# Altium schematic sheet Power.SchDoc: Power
size B; Date: 12/18/2013; DrawnBy: David McCoy; Engineer: David McCoy (Cospan Design); DocumentNumber: 10; Revision: C; SheetNumber: 10; SheetTotal: 10
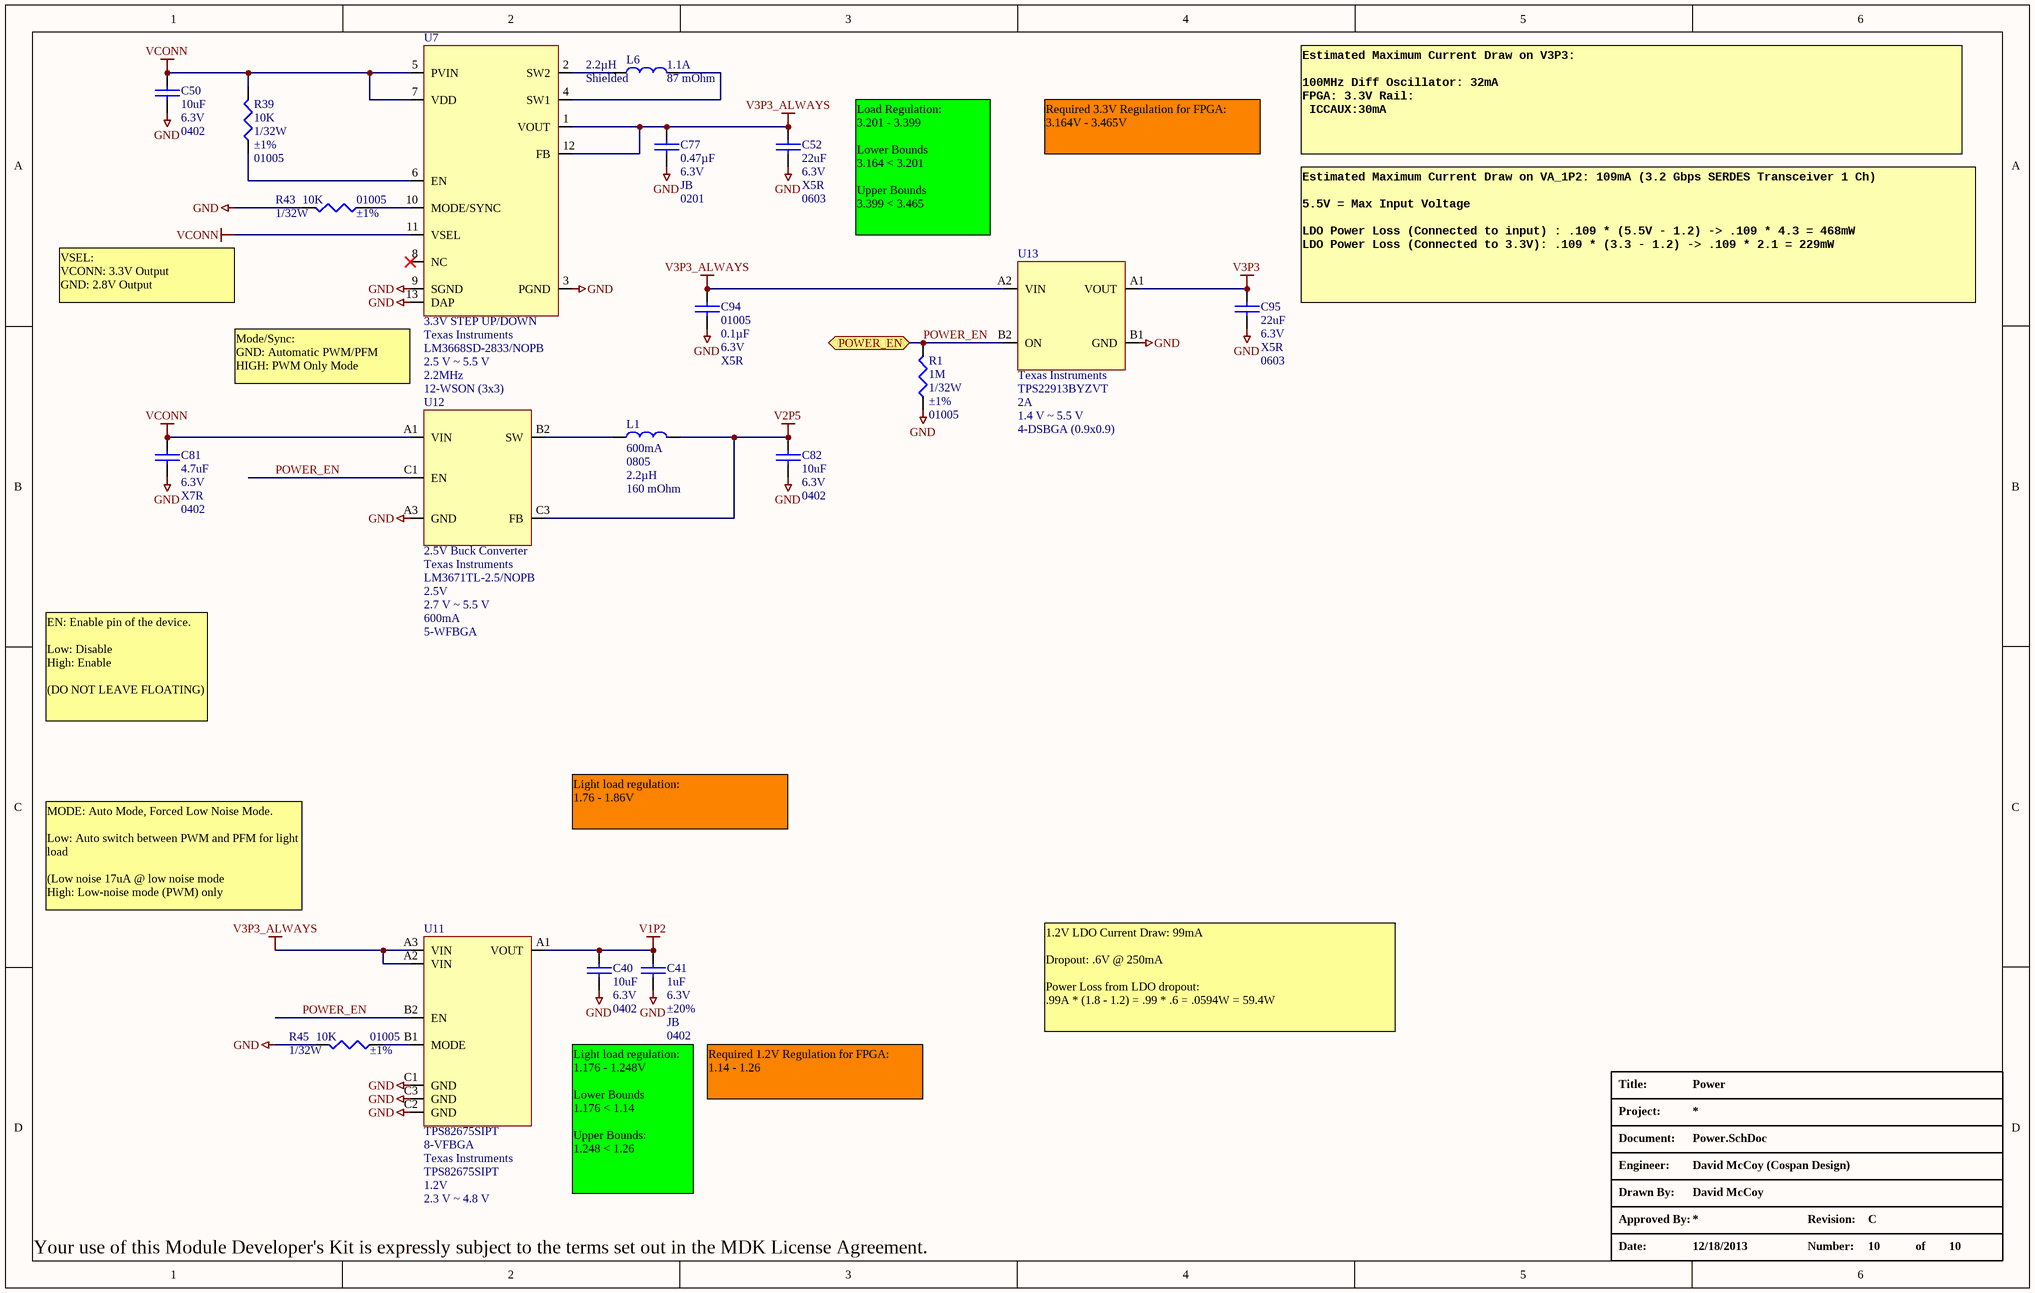
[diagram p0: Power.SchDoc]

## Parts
C40  Voltage - Rated: 6.3V  Package / Case: 0402  [C_0402]  (hidden comment: 10uF)
C41  Voltage - Rated: 6.3V  Tolerance: ±20%  Temperature Coefficient: JB  Package / Case: 0402  [C_0402]  (hidden comment: 1uF)
C50  Voltage - Rated: 6.3V  Package / Case: 0402  [C_0402]  (hidden comment: 10uF)
C52  Voltage - Rated: 6.3V  Temperature Coefficient: X5R  Package / Case: 0603  [C_ERA-0603]  (hidden comment: 22uF)
C77  Voltage - Rated: 6.3V  Temperature Coefficient: JB  Package / Case: 0201  [CAPC0201]  (hidden comment: 0.47µF)
C81  Voltage - Rated: 6.3V  Temperature Coefficient: X7R  Package / Case: 0402  [C_0402]  (hidden comment: 4.7uF)
C82  Voltage - Rated: 6.3V  Package / Case: 0402  [C_0402]  (hidden comment: 10uF)
C94  Package / Case: 01005  Capacitance: 0.1µF  Voltage - Rated: 6.3V  Temperature Coefficient: X5R  [C_01005]  (hidden comment: 0.1uF)
C95  Voltage - Rated: 6.3V  Temperature Coefficient: X5R  Package / Case: 0603  [C_ERA-0603]  (hidden comment: 22uF)
L1  Current: 600mA  Package / Case: 0805  Inductance: 2.2µH  DC Resistance (DCR): 160 mOhm  [C_ERA-0805]  (hidden comment: 2.2uH)
L6  Inductance: 2.2µH  Current - Saturation: 1.1A  Shielding: Shielded  DC Resistance (DCR): 87 mOhm  [L_SMD_2.2uH]  (hidden comment: 2.2uH Wirewound)
R1  Resistance In Ohms: 1M  Power (Watts): 1/32W  Tolerance: ±1%  Case: 01005  [R_01005]  (hidden comment: 1M Ohms)
R39  Power (Watts): 1/32W  Tolerance: ±1%  Case: 01005  [R_01005]  (hidden comment: 10K)
R43  Power (Watts): 1/32W  Tolerance: ±1%  Case: 01005  [R_01005]  (hidden comment: 10K)
R45  Power (Watts): 1/32W  Tolerance: ±1%  Case: 01005  [R_01005]  (hidden comment: 10K)
U7  3.3V STEP UP/DOWN  Manufacturer: Texas Instruments  Manufacturer Part Number: LM3668SD-2833/NOPB  Voltage - Input: 2.5 V ~ 5.5 V  Frequency - Switching: 2.2MHz  Supplier Device Package: 12-WSON (3x3)  [QFN40P300X300X80_HS-13L]
U11  TPS82675SIPT  Package / Case: 8-VFBGA  Manufacturer: Texas Instruments  Voltage - Output: 1.2V  Voltage - Input: 2.3 V ~ 4.8 V  [MICRP SIP]
U12  2.5V Buck Converter  Manufacturer: Texas Instruments  Manufacturer Part Number: LM3671TL-2.5/NOPB  Voltage - Output: 2.5V  Voltage - Input: 2.7 V ~ 5.5 V  Current - Output: 600mA  Package / Case: 5-WFBGA  [BGA4C50P2X2_105X138X60]
U13  Manufacturer: Texas Instruments  Manufacturer Part Number: TPS22913BYZVT  Current Limit: 2A  Voltage - Input: 1.4 V ~ 5.5 V  Supplier Device Package: 4-DSBGA (0.9x0.9)  [DSBGA4 _.5MM]  (hidden comment: Power Switch)

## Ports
POWER_EN

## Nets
GND: C40.1 C41.1 C50.1 C52.1 C77.1 C81.1 C82.1 C94.1 C95.1 R1.2 R43.1 R45.1 U7.3(PGND) U7.9(SGND) U7.13(DAP) U11.C1(GND) U11.C2(GND) U11.C3(GND) U12.A3(GND) U13.B1(GND)
V1P2: C40.2 C41.2 U11.A1(VOUT)
V2P5: C82.2 L1.2 U12.C3(FB)
V3P3: C95.2 U13.A1(VOUT)
V3P3_ALWAYS: C52.2 C77.2 C94.2 U7.1(VOUT) U7.12(FB) U11.A2(VIN) U11.A3(VIN) U13.A2(VIN)
VCONN: C50.2 C81.2 R39.1 U7.5(PVIN) U7.7(VDD) U7.11(VSEL) U12.A1(VIN)
POWER_EN: R1.1 U11.B2(EN) U12.C1(EN) U13.B2(ON) ; port POWER_EN
NetL1_1: L1.1 U12.B2(SW)
NetL6_1: L6.1 U7.2(SW2)
NetL6_2: L6.2 U7.4(SW1)
NetR39_2: R39.2 U7.6(EN)
NetR43_2: R43.2 U7.10(MODE/SYNC)
NetR45_2: R45.2 U11.B1(MODE)

Not connected (* = marked no-connect by the designer): U7 8(NC)*

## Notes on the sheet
- Required 3.3V Regulation for FPGA:
  3.164V - 3.465V
- Estimated Maximum Current Draw on V3P3:
  100MHz Diff Oscillator: 32mA
  FPGA: 3.3V Rail:
  ICCAUX:30mA
- Load Regulation:
  3.201 - 3.399
  Lower Bounds
  3.164 < 3.201
  Upper Bounds
  3.399 < 3.465
- VSEL:
  VCONN: 3.3V Output
  GND: 2.8V Output
- Estimated Maximum Current Draw on VA_1P2: 109mA (3.2 Gbps SERDES Transceiver 1 Ch)
  5.5V = Max Input Voltage
  LDO Power Loss (Connected to input) : .109 * (5.5V - 1.2) -> .109 * 4.3 = 468mW
  LDO Power Loss (Connected to 3.3V): .109 * (3.3 - 1.2) -> .109 * 2.1 = 229mW
- (near U7) Mode/Sync:
  GND: Automatic PWM/PFM
  HIGH: PWM Only Mode
- EN: Enable pin of the device.
  Low: Disable
  High: Enable
  (DO NOT LEAVE FLOATING)
- Light load regulation:
  1.76 - 1.86V
- MODE: Auto Mode, Forced Low Noise Mode.
  Low: Auto switch between PWM and PFM for light load
  (Low noise 17uA @ low noise mode
  High: Low-noise mode (PWM) only
- 1.2V LDO Current Draw: 99mA
  Dropout: .6V @ 250mA
  Power Loss from LDO dropout:
  .99A * (1.8 - 1.2) = .99 * .6 = .0594W = 59.4W
- Required 1.2V Regulation for FPGA:
  1.14 - 1.26
- (near U11) Light load regulation:
  1.176 - 1.248V
  Lower Bounds
  1.176 < 1.14
  Upper Bounds:
  1.248 < 1.26

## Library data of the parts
C40 C50 C82 = C_0402_10uF: CAP CER 10UF 4V 20% X5R 0402; Manufacturer: Taiyo Yuden; Manufacturer Part Number: AMK105CBJ106MV-F
C41 = C_0402_1uF: CAP CER 1UF 6.3V 20% JB 0402; Manufacturer: TDK Corporation; Manufacturer Part Number: C1005JB0J105M050BB
C52 C95 = C_0603_22uF: CAP CER 22UF 6.3V 20% X5R 0603; Manufacturer: TDK Corporation; Manufacturer Part Number: C1608X5R0J226M080AC
C77 = C_0201_0.47µF: CAP CER 0.47UF 6.3V 20% JB 0201; Manufacturer: TDK Corporation; Manufacturer Part Number: C0603JB0J474M030BC
C81 = C_0402_4.7uF: CAP CER 4.7UF 6.3V 10% X7R 0603; Manufacturer: Samsung Electro-Mechanics America, Inc; Manufacturer Part Number: CL10B475KQ8NQNC
C94 = C_01005_0.1uF: CAP CER 0.1UF 6.3V 20% X5R 01005; Manufacturer: TDK Corporation; Manufacturer Part Number: C0402X5R0J104M020BC
L1 = L_0805_2.2uH_160mOhm: INDUCTOR MULTILAYER 2.2UH 0805; Manufacturer: TDK Corporation; Manufacturer Part Number: MLZ2012M2R2H; Material - Core: Ferrite; Tolerance: ±20%; Current - Saturation: 400mA; Shielding: Shielded; Frequency - Self Resonant: 100MHz; Frequency - Test: 2MHz
L6 = L_SMD_2.2uH: COIL CHOKE 2.2UH SHIELDED SMD; Manufacturer: Panasonic Electronic Components; Manufacturer Part Number: ELL-VFG2R2NC; Tolerance: ±30%; Current Rating: 1.4A; Frequency - Test: 100kHz
R1 = R_01005_1M: RES 1M OHM 1/32W 1% 01005 SMD; Manufacturer: Yageo; Manufacturer Part Number: RC0100FR-071ML; Temperature Coefficient: ±250ppm/°C
R39 R43 R45 = R_01005_10K: RES 10K OHM 1/32W 1% 01005; Manufacturer: Samsung Electro-Mechanics America, Inc; Manufacturer Part Number: RC0402F103CS; Temperature Coefficient: ±250ppm/°C
U7 = U_LM3668SD-2833/NOPB: IC REG BUCK BST SYNC ADJ 12-LLP; Output Type: Adjustable; Number of Outputs: 1; Voltage - Output: 2.8 V ~ 3.3 V; PWM Type: Voltage Mode; Current - Output: 1A; Synchronous Rectifier: Yes
U11 = U_TPS82675SIPT: IC REG BUCK SYNC 1.2V 0.6A 8USIP; Output Type: Fixed; Number of Outputs: 1; PWM Type: Voltage Mode; Frequency - Switching: 5.45MHz; Current - Output: 600mA; Synchronous Rectifier: Yes
U12 = U_LM3671TL-2.5/NOPB: IC REG BUCK SYNC 2.5V 0.6A 5USMD; Output Type: Fixed; Number of Outputs: 1; PWM Type: Voltage Mode; Frequency - Switching: 2MHz; Synchronous Rectifier: Yes
U13 = U_TPS22913BYZVT: IC LOAD SWITCH 5V 4DSBGA; Number of Outputs: 1; Rds (On): 80 mOhm; Internal Switch(s): Yes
